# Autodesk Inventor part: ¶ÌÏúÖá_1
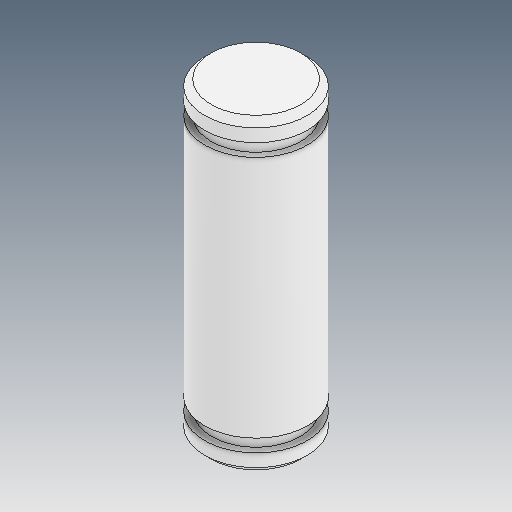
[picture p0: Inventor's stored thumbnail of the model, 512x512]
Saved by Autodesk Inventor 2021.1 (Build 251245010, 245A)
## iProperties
Created: 2021-05
Part Number: ¶ÌÏúÖá_1
Material: Ogólny
Document SubType Name: Modeling
Designer: user
Density: 1 g/cm^3
Appearance: Domyślna
Author: user
Revision Number: ÈÎºÎ
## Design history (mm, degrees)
feature "ÊäÈë1"
node "Bryła1"
